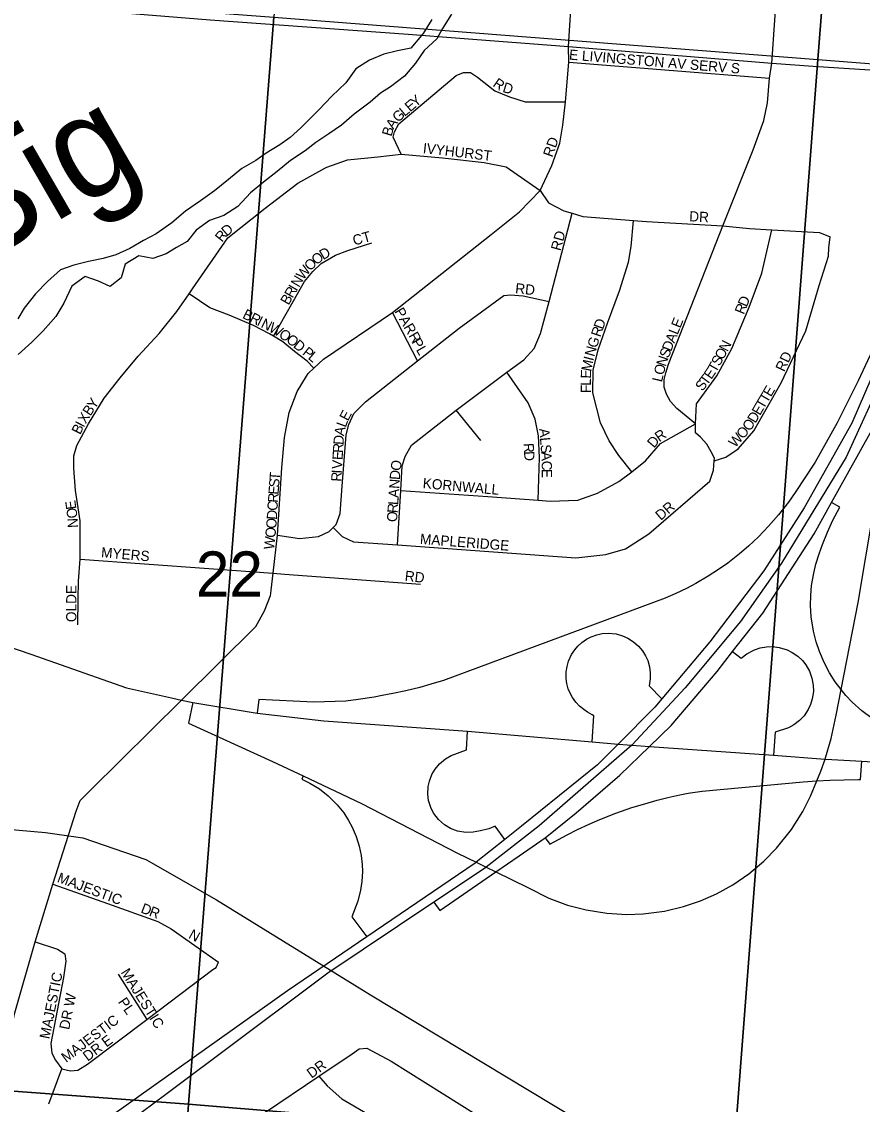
# Model space of a CAD drawing. Extents: x 0 to 34, y 0 to 22.
# Drawn here: x 7.677 to 8.457, y 18.975 to 19.979 of the extents above; entities that cross this region are included whole.
import ezdxf

# ---------------------------------------------------------------- set-up
doc = ezdxf.new("R2010")
doc.units = 0
for name, color, linetype in [('GM_X_City_Street', 7, 'Continuous'), ('GM_X_City_Street_Text', 7, 'Continuous'), ('GM_X_Interchange_Ramps', 7, 'Continuous'), ('GM_X_Interstate_Route', 7, 'Continuous'), ('GM_X_Major_River', 7, 'Continuous'), ('GM_X_Major_River_Text', 7, 'Continuous'), ('GM_X_Rail_Line', 7, 'Continuous'), ('GM_X_Section', 7, 'Continuous'), ('GM_X_Section_Text', 7, 'Continuous')]:
    doc.layers.add(name, color=color, linetype=linetype)

msp = doc.modelspace()

# ---------------------------------------------------------------- linework, layer by layer
at = {"layer": 'GM_X_City_Street'}
for points in [[(8.1845, 19.9557), (8.1882, 20.0146), (8.1995, 20.081), (8.2032, 20.1018)], [(8.3735, 19.9444), (8.3756, 19.9758), (8.3776, 20.0015), (8.3804, 20.0146), (8.3867, 20.0283), (8.3936, 20.0434), (8.3983, 20.0587), (8.4001, 20.0777), (8.4005, 20.0988), (8.4004, 20.0995)], [(7.4865, 20.0093), (7.6452, 19.9972), (7.8522, 19.9804), (8.0357, 19.9671), (8.0837, 19.9634)], [(7.9429, 19.6524), (7.943, 19.6526), (7.9483, 19.6576), (7.9571, 19.6658), (8.0214, 19.7092), (8.1128, 19.7813), (8.139, 19.8026), (8.1583, 19.8223), (8.1691, 19.8455), (8.1766, 19.8663), (8.1793, 19.8828), (8.1817, 19.9046), (8.185, 19.9414), (8.1845, 19.9557)], [(8.0837, 19.9634), (8.1845, 19.9557), (8.3733, 19.9405), (8.4117, 19.9375), (8.4643, 19.9343), (8.5377, 19.9336), (8.551, 19.9336), (8.5626, 19.9333), (8.6189, 19.9334), (8.7115, 19.9328)], [(8.3023, 19.6059), (8.2851, 19.6199), (8.2791, 19.6265), (8.2754, 19.6334), (8.2734, 19.6399), (8.2734, 19.6468), (8.2749, 19.6531), (8.2775, 19.6611), (8.3087, 19.7407), (8.3278, 19.7894), (8.3558, 19.8601), (8.3657, 19.8873), (8.3692, 19.9036), (8.3711, 19.9263), (8.3733, 19.9405), (8.3735, 19.9444)], [(8.185, 19.9414), (8.3711, 19.9263)], [(8.0293, 19.8559), (8.022, 19.8716), (8.0232, 19.8768), (8.0271, 19.884), (8.0802, 19.9288), (8.0871, 19.9317), (8.0935, 19.9316), (8.1002, 19.9273), (8.1162, 19.9148), (8.1297, 19.9092), (8.1444, 19.9044), (8.1817, 19.9046)], [(8.0076, 19.8536), (8.0293, 19.8559), (8.0677, 19.8524), (8.1062, 19.8482), (8.1267, 19.8441), (8.1583, 19.8223), (8.1659, 19.8109), (8.1801, 19.8034), (8.188, 19.8011), (8.1978, 19.7981), (8.2449, 19.7944), (8.2571, 19.7935), (8.3278, 19.7894), (8.3526, 19.787), (8.3734, 19.7858), (8.4175, 19.7834), (8.4273, 19.7794)], [(7.9585, 19.843), (7.9602, 19.844), (7.9796, 19.8508), (8.0076, 19.8536)], [(7.7294, 19.4193), (7.7295, 19.4432), (7.7298, 19.4599), (7.7314, 19.4804), (7.7314, 19.4998), (7.7313, 19.5157), (7.727, 19.5439), (7.7255, 19.5648), (7.7257, 19.5762), (7.7282, 19.5856), (7.7392, 19.6059), (7.7536, 19.6295), (7.7684, 19.6486), (7.7854, 19.6687), (7.8047, 19.6896), (7.821, 19.7101), (7.8325, 19.7265), (7.8358, 19.7311), (7.8685, 19.7783), (7.9031, 19.806), (7.9334, 19.8289), (7.9584, 19.843), (7.9585, 19.843)], [(8.0258, 19.4935), (8.029, 19.5441), (8.0302, 19.5669), (8.033, 19.5756), (8.0389, 19.5861), (8.0803, 19.6185), (8.1273, 19.6536), (8.143, 19.6652), (8.1526, 19.6757), (8.1586, 19.6896), (8.1667, 19.7194), (8.188, 19.8011)], [(8.2433, 19.5614), (8.2312, 19.5765), (8.2224, 19.59), (8.2144, 19.6068), (8.207, 19.6347), (8.2074, 19.6556), (8.212, 19.6744), (8.2208, 19.6993), (8.232, 19.7291), (8.2401, 19.7559), (8.2426, 19.7702), (8.2449, 19.7944)], [(8.3023, 19.6059), (8.3032, 19.6244), (8.3222, 19.6502), (8.336, 19.6757), (8.3522, 19.7141), (8.3639, 19.7457), (8.3734, 19.7858)], [(7.9109, 19.6872), (7.9395, 19.7377), (7.9473, 19.747), (7.955, 19.7545), (7.9684, 19.7622), (7.9798, 19.7665), (8.0022, 19.7736)], [(8.3197, 19.5716), (8.3306, 19.5748), (8.342, 19.5826), (8.3564, 19.5994), (8.3818, 19.644), (8.4047, 19.6921), (8.4173, 19.734), (8.4258, 19.7612), (8.4263, 19.7691), (8.4273, 19.7794)], [(7.9483, 19.6576), (7.9422, 19.664), (7.9303, 19.673), (7.9195, 19.6819), (7.9109, 19.6872), (7.9072, 19.6894), (7.8922, 19.6969), (7.8697, 19.7065), (7.8517, 19.7133), (7.8325, 19.7265)], [(7.9147, 19.5024), (7.9351, 19.4994), (7.9525, 19.5013), (7.9625, 19.506), (7.9661, 19.5096), (7.969, 19.5124), (7.9726, 19.5225), (7.9747, 19.5479), (7.9783, 19.5957), (7.9807, 19.6051), (7.9855, 19.6153), (7.9963, 19.6261), (8.0444, 19.6641), (8.0831, 19.6945), (8.1245, 19.7248), (8.1309, 19.7254), (8.1426, 19.7244), (8.1667, 19.7194)], [(8.0444, 19.6641), (8.0214, 19.7092)], [(8.1563, 19.535), (8.1578, 19.5746), (8.1567, 19.5947), (8.1536, 19.61), (8.1471, 19.6253), (8.1273, 19.6536)], [(7.9086, 19.4514), (7.9105, 19.4673), (7.9147, 19.5024), (7.9187, 19.5649), (7.9211, 19.593), (7.9254, 19.6162), (7.9327, 19.6359), (7.9414, 19.65), (7.9429, 19.6524)], [(8.1033, 19.5905), (8.0803, 19.6185)], [(7.9661, 19.5096), (7.9745, 19.5012), (7.985, 19.4965), (8.0258, 19.4935), (8.1915, 19.4816), (8.2191, 19.4845), (8.2374, 19.4898), (8.2592, 19.5038), (8.3157, 19.5527), (8.319, 19.5629), (8.3197, 19.5716), (8.3199, 19.5739), (8.317, 19.58), (8.313, 19.587), (8.3071, 19.5935), (8.3023, 19.5974), (8.3023, 19.6059)], [(8.029, 19.5441), (8.1098, 19.5383), (8.1563, 19.535), (8.1676, 19.5341), (8.1933, 19.5351), (8.2116, 19.5416), (8.2314, 19.5522), (8.2433, 19.5614), (8.256, 19.5714), (8.2699, 19.5875), (8.3023, 19.6059)], [(7.7314, 19.4804), (7.9105, 19.4673), (7.9209, 19.4665)], [(7.9209, 19.4665), (8.0473, 19.4572)], [(7.6191, 18.9248), (7.6485, 18.9786), (7.6581, 18.9994), (7.6635, 19.0256), (7.6709, 19.0594), (7.6896, 19.1255), (7.7061, 19.1787), (7.7276, 19.2464), (7.7314, 19.2566), (7.7409, 19.2661), (7.8255, 19.3496), (7.8945, 19.4177), (7.9025, 19.4324), (7.9079, 19.4465), (7.9083, 19.4486), (7.9086, 19.4514)], [(7.7061, 19.1787), (7.7567, 19.161), (7.8036, 19.1441), (7.8159, 19.1374), (7.8599, 19.1065)], [(7.6896, 19.1255), (7.7105, 19.1187), (7.7172, 19.1143), (7.7182, 19.1075), (7.716, 19.0924), (7.7042, 19.0311), (7.7051, 19.022), (7.7084, 19.0155), (7.7143, 19.0077)], [(7.7143, 19.0077), (7.7226, 19.0057), (7.7294, 19.0063), (7.7382, 19.0118), (7.7933, 19.0534), (7.8545, 19.0998), (7.8575, 19.1017), (7.8599, 19.1065)], [(7.7667, 19.0955), (7.7933, 19.0534)], [(7.7277, 18.8279), (7.7297, 18.8355), (7.7341, 18.846), (7.7403, 18.855), (7.7619, 18.87), (7.8538, 18.9339), (7.9024, 18.9667), (7.9529, 19.0008), (7.9837, 19.0216), (7.9903, 19.026), (7.9974, 19.0266), (8.0199, 19.0148), (8.1304, 18.9454), (8.1355, 18.9384), (8.1377, 18.9334), (8.1402, 18.9266)], [(7.7023, 18.975), (7.7143, 19.0077)], [(7.9529, 19.0008), (7.9605, 18.9917), (7.9742, 18.9797), (8.0018, 18.9635), (8.0623, 18.9266), (8.0709, 18.9189), (8.0768, 18.9104), (8.0807, 18.8978), (8.0853, 18.8848), (8.092, 18.8759), (8.1039, 18.8707), (8.122, 18.8666), (8.1401, 18.864), (8.1533, 18.8621), (8.1687, 18.8588), (8.1848, 18.8501), (8.248, 18.8135), (8.2633, 18.8049), (8.2742, 18.8035), (8.2864, 18.8028)]]:
    msp.add_lwpolyline(points, dxfattribs=at)
at = {"layer": 'GM_X_Interchange_Ramps'}
for points in [[(8.4752, 19.6927), (8.4533, 19.6457), (8.4339, 19.6068), (8.4136, 19.5704), (8.395, 19.542), (8.3887, 19.5331), (8.3794, 19.5213), (8.3703, 19.5108), (8.3608, 19.501), (8.3516, 19.4924), (8.3433, 19.4853), (8.3323, 19.4767), (8.3239, 19.4707), (8.3142, 19.4644), (8.3026, 19.4576), (8.2942, 19.4531), (8.2843, 19.4483), (8.2744, 19.444), (8.0687, 19.3679), (8.0569, 19.3642), (8.0465, 19.3612), (8.0336, 19.3581), (8.0217, 19.3556), (8.0117, 19.3538), (8.0041, 19.3523), (7.9895, 19.3501), (7.9778, 19.3487), (7.9483, 19.3476), (7.8971, 19.3501), (7.8957, 19.3373)], [(8.4719, 19.663), (8.4476, 19.6063), (8.4033, 19.5279), (8.3659, 19.4694), (8.3158, 19.4036), (8.2711, 19.3506), (8.2647, 19.343), (8.2308, 19.3088), (8.2115, 19.2894), (8.141, 19.2325), (8.1255, 19.2202), (8.0989, 19.1991), (8.0981, 19.1984), (7.9973, 19.1299), (7.9239, 19.08), (7.7484, 18.9552)], [(8.0595, 19.1621), (8.0651, 19.1544), (8.117, 19.1903), (8.1387, 19.2052), (8.1629, 19.2219), (8.1917, 19.245), (8.2321, 19.2799), (8.2598, 19.3066), (8.2799, 19.3261), (8.3224, 19.3761), (8.3369, 19.3945), (8.365, 19.4303), (8.4125, 19.5037), (8.4287, 19.5328), (8.4436, 19.5593), (8.4661, 19.5999)], [(8.4665, 19.3324), (8.4568, 19.3395), (8.4478, 19.3477), (8.442, 19.3538), (8.4377, 19.3593), (8.4321, 19.3665), (8.4268, 19.3748), (8.4218, 19.3843), (8.4175, 19.3945), (8.4145, 19.4036), (8.412, 19.4134), (8.4099, 19.4267), (8.4092, 19.4374), (8.4094, 19.4466), (8.4102, 19.4559), (8.4121, 19.4674), (8.4142, 19.4757), (8.4172, 19.4852), (8.4203, 19.494), (8.4248, 19.5052), (8.43, 19.5165), (8.4362, 19.5286), (8.4287, 19.5328)], [(7.836, 19.3473), (7.8319, 19.3283), (7.91, 19.2926), (7.9384, 19.2792), (7.9926, 19.2537), (8.0816, 19.2075), (8.0989, 19.1991), (8.1083, 19.1945), (8.117, 19.1903), (8.1469, 19.1757), (8.1664, 19.1659), (8.1838, 19.1594), (8.2009, 19.1549), (8.2202, 19.1518), (8.2387, 19.1508), (8.2539, 19.1513), (8.2737, 19.1539), (8.2914, 19.1581), (8.307, 19.1633), (8.3219, 19.1699), (8.337, 19.1783), (8.352, 19.1885), (8.3658, 19.2002), (8.3776, 19.2121), (8.3915, 19.2295), (8.4019, 19.2462), (8.4091, 19.2605), (8.4149, 19.2746), (8.4186, 19.2836), (8.4226, 19.2949), (8.423, 19.2959), (8.4283, 19.314), (8.4331, 19.3355), (8.4377, 19.3593), (8.4533, 19.44), (8.4679, 19.5267)], [(8.2066, 19.3109), (8.208, 19.3351), (8.2065, 19.3358), (8.2021, 19.3384), (8.1987, 19.3407), (8.1948, 19.3439), (8.1913, 19.3476), (8.1882, 19.3519), (8.1858, 19.3565), (8.1844, 19.3601), (8.1831, 19.365), (8.1824, 19.3696), (8.1825, 19.3758), (8.1832, 19.3807), (8.1846, 19.3858), (8.1874, 19.3919), (8.1904, 19.3963), (8.1933, 19.3997), (8.197, 19.4031), (8.2013, 19.406), (8.2057, 19.4084), (8.2109, 19.4102), (8.2157, 19.4112), (8.2216, 19.4116), (8.2287, 19.411), (8.2348, 19.4093), (8.2397, 19.4071), (8.245, 19.4037), (8.2495, 19.3997), (8.2533, 19.3952), (8.2561, 19.3907), (8.2581, 19.3862), (8.2597, 19.3805), (8.2605, 19.3748), (8.2604, 19.3692), (8.2594, 19.3628), (8.2711, 19.3506)], [(8.3369, 19.3945), (8.3448, 19.3886), (8.3502, 19.3924), (8.3572, 19.3962), (8.3624, 19.3979), (8.3682, 19.399), (8.3739, 19.3992), (8.3801, 19.3984), (8.3875, 19.3962), (8.3922, 19.3938), (8.3974, 19.3903), (8.4016, 19.3862), (8.4047, 19.3824), (8.4082, 19.3763), (8.4105, 19.37), (8.4117, 19.3634), (8.4118, 19.3577), (8.4108, 19.3506), (8.4092, 19.3455), (8.407, 19.3408), (8.4032, 19.3351), (8.3988, 19.3305), (8.3937, 19.3266), (8.3887, 19.3239), (8.3765, 19.3197), (8.3748, 19.2984)], [(8.1255, 19.2202), (8.1166, 19.2325), (8.1106, 19.2303), (8.1029, 19.2282), (8.096, 19.2271), (8.0892, 19.2267), (8.0816, 19.228), (8.075, 19.2305), (8.0695, 19.2338), (8.0638, 19.2389), (8.0596, 19.2445), (8.0572, 19.249), (8.0548, 19.2566), (8.0541, 19.2622), (8.0545, 19.2693), (8.0555, 19.2743), (8.0579, 19.2806), (8.0608, 19.2855), (8.065, 19.2906), (8.0703, 19.295), (8.0757, 19.2981), (8.09, 19.3034), (8.0907, 19.3209)], [(8.1629, 19.2219), (8.1672, 19.216), (8.1832, 19.2246), (8.1928, 19.2294), (8.2039, 19.2346), (8.2136, 19.2388), (8.2285, 19.2447), (8.2434, 19.2499), (8.2553, 19.2535), (8.2668, 19.2567), (8.2768, 19.2592), (8.2879, 19.2616), (8.2957, 19.2631), (8.3085, 19.2652), (8.4024, 19.2739), (8.4149, 19.2746), (8.427, 19.2752), (8.4537, 19.2759), (8.4555, 19.2758), (8.4568, 19.2928)], [(7.9384, 19.2792), (7.9371, 19.2763), (7.9447, 19.2726), (7.9534, 19.2672), (7.9617, 19.2607), (7.97, 19.2525), (7.976, 19.2449), (7.9805, 19.238), (7.9839, 19.2316), (7.9876, 19.223), (7.9904, 19.214), (7.9922, 19.2054), (7.9931, 19.1972), (7.9933, 19.1905), (7.9928, 19.1814), (7.9916, 19.1732), (7.989, 19.1632), (7.9836, 19.1485), (7.9973, 19.1299)]]:
    msp.add_lwpolyline(points, dxfattribs=at)
at = {"layer": 'GM_X_Interstate_Route'}
for points in [[(8.6809, 20.727), (8.6471, 20.5176), (8.6121, 20.3042), (8.5692, 20.0743), (8.551, 19.9336), (8.5296, 19.8139), (8.5082, 19.7315), (8.4785, 19.6541), (8.4423, 19.575), (8.3822, 19.4765), (8.3443, 19.4226), (8.2928, 19.3608), (8.2434, 19.3078)], [(6.8515, 19.5006), (6.856, 19.501), (6.9003, 19.5063), (7.0139, 19.5201), (7.0525, 19.5234), (7.0975, 19.5249), (7.1506, 19.5247), (7.1982, 19.5221), (7.2409, 19.5171), (7.2883, 19.5109), (7.3176, 19.5063), (7.3568, 19.4984), (7.3997, 19.4881), (7.4592, 19.4703), (7.5217, 19.4482), (7.6858, 19.3921), (7.7744, 19.3608), (7.8161, 19.3516), (7.8255, 19.3496)], [(7.8255, 19.3496), (7.836, 19.3473), (7.8957, 19.3373), (7.9575, 19.3303), (8.0907, 19.3209)], [(8.0907, 19.3209), (8.2066, 19.3109), (8.2308, 19.3088), (8.2434, 19.3078)], [(8.2434, 19.3078), (8.215, 19.2829), (8.1573, 19.2331), (8.1083, 19.1945), (8.1075, 19.1939), (8.0595, 19.1621)], [(8.2434, 19.3078), (8.2598, 19.3066), (8.3748, 19.2984), (8.4226, 19.2949), (8.4233, 19.2949), (8.4568, 19.2928)], [(8.4568, 19.2928), (8.4568, 19.2928), (8.5293, 19.2882)], [(8.0595, 19.1621), (8.0595, 19.1621), (7.9613, 19.0963), (7.9438, 19.0832)], [(7.9438, 19.0832), (7.8108, 18.9839), (7.7568, 18.9437)]]:
    msp.add_lwpolyline(points, dxfattribs=at)
at = {"layer": 'GM_X_Major_River'}
for points in [[(8.0759, 19.9858), (8.0676, 19.9725), (8.0623, 19.963), (8.0505, 19.9521), (8.0426, 19.9403), (8.0323, 19.9282), (8.0194, 19.9183)], [(8.0578, 19.9809), (8.0498, 19.968), (8.0384, 19.9544), (8.0259, 19.9517), (8.0131, 19.9487), (7.9998, 19.943)], [(7.9998, 19.943), (7.9873, 19.9351), (7.9778, 19.9222), (7.9649, 19.9097), (7.9528, 19.8972), (7.9411, 19.8854)], [(8.0194, 19.9183), (8.01, 19.9126), (8.0005, 19.9043), (7.9857, 19.893), (7.974, 19.8827), (7.9622, 19.8748), (7.9501, 19.8668), (7.9403, 19.8589), (7.9266, 19.8502), (7.9141, 19.8399), (7.9016, 19.8301), (7.8895, 19.8202), (7.8778, 19.8073), (7.8649, 19.799), (7.8516, 19.7945), (7.8391, 19.7854), (7.8308, 19.7748), (7.8209, 19.7695), (7.8111, 19.7634), (7.799, 19.7593), (7.7858, 19.7616), (7.7733, 19.754), (7.7694, 19.7411), (7.7592, 19.7331), (7.7483, 19.7381), (7.7362, 19.7426), (7.7237, 19.7336), (7.7164, 19.7176), (7.7089, 19.7055), (7.6971, 19.6922), (7.6865, 19.6816), (7.674, 19.6702)], [(7.9411, 19.8854), (7.9361, 19.8805), (7.9263, 19.8714), (7.9168, 19.8646), (7.904, 19.857), (7.8945, 19.8502), (7.8816, 19.8426), (7.8691, 19.8324), (7.8562, 19.8218), (7.843, 19.8127), (7.8293, 19.8032), (7.8164, 19.7922), (7.8021, 19.782), (7.7903, 19.776), (7.7774, 19.7684), (7.7646, 19.7627), (7.7528, 19.7593), (7.7392, 19.7563), (7.7256, 19.7529), (7.7131, 19.7488), (7.701, 19.7378), (7.69, 19.7264), (7.6794, 19.7131), (7.6737, 19.7033)]]:
    msp.add_lwpolyline(points, dxfattribs=at)
at = {"layer": 'GM_X_Rail_Line'}
msp.add_lwpolyline([(6.6636, 19.3159), (7.0524, 19.2852), (7.6258, 19.2334), (7.6994, 19.2269), (7.7338, 19.2217), (7.7924, 19.2016), (7.8578, 19.1642), (8.0007, 19.0761), (8.2969, 18.8979), (8.814, 18.5835), (9.2779, 18.3027), (9.4, 18.2291)], dxfattribs=at)
at = {"layer": 'GM_X_Section'}
for points in [[(7.9844, 20.9), (7.911, 19.983), (8.4159, 19.9436), (8.4907, 20.9)], [(8.4907, 20.9), (8.4159, 19.9436), (8.9298, 19.9037), (9.007, 20.8932), (8.9162, 20.9)]]:
    msp.add_lwpolyline(points, dxfattribs=at)
for points in [[(7.4047, 20.0213), (7.911, 19.983), (7.832, 18.9749), (7.324, 19.0124)], [(7.911, 19.983), (8.4159, 19.9436), (8.3382, 18.9328), (7.832, 18.9749)], [(8.4159, 19.9436), (8.9298, 19.9037), (8.8584, 18.8902), (8.3382, 18.9328)], [(7.324, 19.0124), (7.832, 18.9749), (7.7594, 17.9553), (7.2561, 17.997)], [(7.832, 18.9749), (8.3382, 18.9328), (8.2612, 17.9133), (7.7594, 17.9553)]]:
    msp.add_lwpolyline(points, close=True, dxfattribs=at)

# ---------------------------------------------------------------- texts
at = {"layer": 'GM_X_City_Street_Text'}
for s, rotation, p in [('E LIVINGSTON AV SERV S', 355.2921, (8.1848, 19.9437)), ('R', 325.1313, (8.1137, 19.9195)), ('D', 343.3944, (8.1228, 19.9138)), ('E', 40.1595, (8.0376, 19.8947)), ('Y', 40.1737, (8.0427, 19.899)), ('G', 41.7842, (8.0263, 19.8849)), ('L', 40.1449, (8.0325, 19.8904)), ('A', 56.3584, (8.0221, 19.8784)), ('B', 73.7777, (8.0203, 19.8719)), ('IVYHURST', 353.3863, (8.0491, 19.857)), ('RD', 70.568, (8.1696, 19.8525)), ('DR', 356.989, (8.2964, 19.7937)), ('R', 51.5222, (7.8631, 19.7737)), ('D', 40.9782, (7.8675, 19.7792)), ('CT', 15.5291, (7.9858, 19.7711)), ('RD', 74.4709, (8.1771, 19.7657)), ('O', 37.0448, (7.9505, 19.7527)), ('D', 30.3304, (7.9569, 19.7576)), ('W', 51.4216, (7.9384, 19.7387)), ('O', 45.8039, (7.945, 19.747)), ('N', 59.3061, (7.9344, 19.7318)), ('I', 59.8932, (7.9323, 19.7282)), ('RD', 353.9785, (8.1348, 19.727)), ('B', 59.9026, (7.9248, 19.7153)), ('R', 59.8816, (7.9285, 19.7218)), ('D', 66.6522, (8.3499, 19.7136)), ('PARR', 300.1366, (8.0228, 19.7102)), ('R', 67.9461, (8.3472, 19.7067)), ('B', 333.4132, (7.8813, 19.7043)), ('R', 333.3806, (7.888, 19.701)), ('I', 333.4224, (7.8947, 19.6976)), ('N', 333.2492, (7.8984, 19.6957)), ('D', 70.4109, (8.2165, 19.6928)), ('E', 68.4015, (8.2883, 19.694)), ('W', 330.155, (7.9057, 19.6921)), ('O', 327.098, (7.915, 19.6867)), ('R', 71.1099, (8.2141, 19.6857)), ('L', 68.4015, (8.2858, 19.6878)), ('O', 322.7673, (7.9219, 19.6823)), ('D', 322.0809, (7.9285, 19.6773)), ('PL', 299.7432, (8.0386, 19.6819)), ('G', 72.0696, (8.2107, 19.6755)), ('A', 68.3975, (8.2828, 19.6801)), ('N', 63.349, (8.3321, 19.6721)), ('P', 321.7369, (7.937, 19.6706)), ('L', 319.8551, (7.9422, 19.6666)), ('N', 74.6011, (8.2085, 19.6676)), ('S', 68.5741, (8.2773, 19.6661)), ('D', 68.4055, (8.2797, 19.6723)), ('O', 61.3452, (8.3279, 19.6645)), ('M', 78.6901, (8.2056, 19.6539)), ('I', 75.2853, (8.2075, 19.6636)), ('N', 71.724, (8.2747, 19.6584)), ('T', 60.318, (8.3213, 19.6527)), ('S', 61.328, (8.3247, 19.6587)), ('RD', 64.8032, (8.3847, 19.6535)), ('E', 88.333, (8.2054, 19.6477)), ('O', 76.4779, (8.2728, 19.6505)), ('E', 55.6307, (8.3171, 19.6465)), ('L', 89.8075, (8.2054, 19.6411)), ('L', 76.4873, (8.2712, 19.644)), ('S', 53.7256, (8.309, 19.6355)), ('T', 53.7256, (8.313, 19.6408)), ('F', 89.8087, (8.2054, 19.6344)), ('T', 59.6167, (8.369, 19.6245)), ('E', 59.5843, (8.3724, 19.6303)), ('B', 56.97, (7.7409, 19.6125)), ('Y', 56.8799, (7.745, 19.6187)), ('E', 59.5992, (8.3622, 19.613)), ('T', 59.5843, (8.3656, 19.6188)), ('X', 58.7476, (7.7366, 19.6054)), ('E', 62.3229, (7.9799, 19.6078)), ('D', 59.5778, (8.358, 19.6058)), ('B', 63.272, (7.7314, 19.5952)), ('I', 62.4185, (7.7347, 19.6018)), ('L', 69.9492, (7.9778, 19.6019)), ('O', 47.9998, (8.3464, 19.5911)), ('O', 54.8198, (8.3528, 19.5983)), ('D', 86.5364, (7.9758, 19.5861)), ('A', 78.7586, (7.9762, 19.5941)), ('A', 275.2973, (8.1573, 19.6012)), ('L', 275.3074, (8.158, 19.5929)), ('D', 50.0293, (8.2639, 19.5828)), ('R', 34.6399, (8.2688, 19.5887)), ('W', 48.009, (8.3392, 19.5831)), ('R', 86.5343, (7.9753, 19.5786)), ('R', 273.3536, (8.1428, 19.5877)), ('S', 275.281, (8.1586, 19.5863)), ('V', 86.5232, (7.9744, 19.5636)), ('E', 86.5313, (7.9749, 19.572)), ('D', 272.3832, (8.1433, 19.5803)), ('A', 273.3459, (8.1592, 19.5797)), ('D', 86.0857, (8.028, 19.5536)), ('O', 80.9796, (8.0286, 19.5617)), ('C', 270.2429, (8.1597, 19.5716)), ('E', 270, (8.1598, 19.5641)), ('S', 85.9365, (7.916, 19.5465)), ('T', 85.8988, (7.9165, 19.5532)), ('R', 86.5252, (7.9737, 19.552)), ('I', 86.5525, (7.9742, 19.5595)), ('N', 86.0857, (8.0275, 19.5453)), ('KORNWALL', 354.9366, (8.049, 19.5462)), ('E', 85.8988, (7.9155, 19.5399)), ('A', 86.0623, (8.0269, 19.5369)), ('E', 97.762, (7.728, 19.527)), ('C', 85.9161, (7.9144, 19.5249)), ('R', 85.9161, (7.915, 19.5324)), ('L', 86.0888, (8.0265, 19.5303)), ('DR', 40.6039, (8.2702, 19.5157)), ('O', 97.1769, (7.7291, 19.5187)), ('D', 85.9165, (7.9139, 19.5166)), ('O', 86.0841, (8.0254, 19.5145)), ('R', 86.0632, (8.0259, 19.5228)), ('N', 92.6452, (7.7295, 19.5095)), ('O', 85.894, (7.9133, 19.5083)), ('O', 84.8798, (7.9125, 19.4998)), ('MAPLERIDGE', 355.5526, (8.0465, 19.4945)), ('W', 83.3442, (7.9112, 19.4888)), ('MYERS', 355.239, (7.7506, 19.482)), ('RD', 353.6518, (8.0323, 19.4603)), ('OLDE', 90, (7.7279, 19.4219)), ('MAJESTIC', 339.6478, (7.7094, 19.1811)), ('D', 339.27, (7.787, 19.1527)), ('R', 339.2641, (7.7947, 19.1498)), ('N', 330.9557, (7.8313, 19.1293)), ('MAJESTIC', 302.0054, (7.7687, 19.097)), ('MAJESTIC', 78.6901, (7.7029, 19.0347)), ('DR W', 78.6901, (7.7212, 19.0433)), ('PL', 304.6908, (7.7662, 19.0696)), ('MAJESTIC', 37.2077, (7.7184, 19.013)), ('DR E', 36.8699, (7.7384, 19.0141)), ('DR', 36.2494, (7.9461, 18.9983))]:
    msp.add_text(s, height=0.00947, rotation=rotation, dxfattribs=at).set_placement(p)
at = {"layer": 'GM_X_Major_River_Text'}
msp.add_text('Big', height=0.0947, rotation=30.0102, dxfattribs=at).set_placement((7.6335, 19.7493))
at = {"layer": 'GM_X_Section_Text'}
msp.add_text('22', height=0.04186, rotation=0, dxfattribs=at).set_placement((7.8388, 19.4456))

doc.saveas('drawing.dxf')
